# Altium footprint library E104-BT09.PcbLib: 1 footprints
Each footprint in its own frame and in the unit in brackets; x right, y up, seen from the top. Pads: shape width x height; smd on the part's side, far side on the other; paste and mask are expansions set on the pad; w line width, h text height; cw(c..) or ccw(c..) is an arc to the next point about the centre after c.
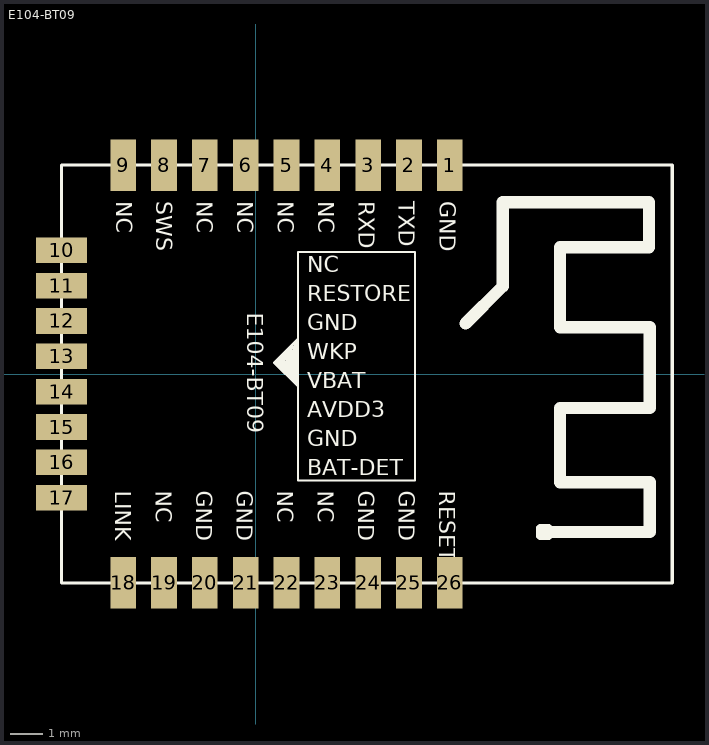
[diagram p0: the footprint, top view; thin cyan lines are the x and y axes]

## E104-BT09 [mm]
pads (26):
  rect 0.8x1.6 smd: 1(6.04,6.5) 2(4.77,6.5) 3(3.5,6.5) 4(2.23,6.5) 5(0.96,6.5) 6(-0.31,6.5) 7(-1.58,6.5) 8(-2.85,6.5) 9(-4.12,6.5) 18(-4.12,-6.5) 19(-2.85,-6.5) 20(-1.58,-6.5) 21(-0.31,-6.5) 22(0.96,-6.5) 23(2.23,-6.5) 24(3.5,-6.5) 25(4.77,-6.5) 26(6.04,-6.5)
  rect 1.6x0.8 smd: 10(-6.04,3.85) 11(-6.04,2.75) 12(-6.04,1.65) 13(-6.04,0.55) 14(-6.04,-0.55) 15(-6.04,-1.65) 16(-6.04,-2.75) 17(-6.04,-3.85)
Top Overlay:
  lines w0.06: 0.621,0.355 0.771,0.355 ; 0.671,0.305 1.271,-0.295 1.271,1.005 ; 0.671,0.405 1.221,0.955 1.221,-0.195 0.721,0.305 0.721,0.405 1.171,0.855 1.171,-0.145 1.121,-0.095 1.121,-0.045 0.771,0.305 0.771,0.405 1.121,0.755 1.121,0.005 0.821,0.305 0.821,0.455 1.021,0.655 1.021,0.155 1.071,0.105 1.071,0.655 0.871,0.455 0.871,0.355 1.021,0.205 0.971,0.205 0.871,0.305 0.871,0.405 0.971,0.505 0.971,0.355 0.971,0.305 0.921,0.355 0.921,0.405 ; 1.321,-3.311 1.321,-0.895 1.321,3.801 ; 1.321,-0.395 0.571,0.355 1.321,1.105 ; 1.33,-3.315 4.953,-3.315 4.953,3.797 1.336,3.797
  lines w0.1: -6.04,-6.5 -6.04,6.5 12.96,6.5 12.96,-6.5 -6.04,-6.5
  lines w0.254: 9.11,-5.045 8.856,-5.045 8.856,-4.791 9.11,-4.791
  lines w0.381: 6.532,1.572 7.688,2.728 7.688,5.344 12.235,5.344 12.235,3.947 9.466,3.947 9.466,1.458 12.26,1.458 12.26,-1.057 9.466,-1.057 9.466,-3.368 12.26,-3.368 12.26,-4.918 8.983,-4.918
  text "E104-BT09" at -0.254,1.905 h0.5
  text "GND" at -1.846,-3.633 h0.5
  text "NC" at -3.106,-3.633 h0.5
  text "GND" at -0.586,-3.633 h0.5
  text "NC" at 0.673,-3.633 h0.5
  text "LINK" at -4.366,-3.633 h0.5
  text "NC" at 1.933,-3.633 h0.5
  text "GND" at 3.193,-3.633 h0.5
  text "GND" at 4.453,-3.633 h0.5
  text "RESET" at 5.713,-3.633 h0.5
  text "NC" at -4.344,5.381 h0.5
  text "SWS" at -3.087,5.381 h0.5
  text "NC" at -1.829,5.381 h0.5
  text "NC" at -0.571,5.381 h0.5
  text "NC" at 0.687,5.381 h0.5
  text "NC" at 1.944,5.381 h0.5
  text "RXD" at 3.202,5.381 h0.5
  text "TXD" at 4.46,5.381 h0.5
  text "GND" at 5.732,5.381 h0.5
  text "BAT-DET" at 1.601,-3.152 h0.5
  text "GND" at 1.601,-2.251 h0.5
  text "AVDD3" at 1.601,-1.349 h0.5
  text "VBAT" at 1.601,-0.447 h0.5
  text "WKP" at 1.601,0.454 h0.5
  text "GND" at 1.601,1.356 h0.5
  text "NC" at 1.601,3.159 h0.5
  text "RESTORE" at 1.601,2.257 h0.5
